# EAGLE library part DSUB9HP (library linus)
9-pin D-SUB card-mounted
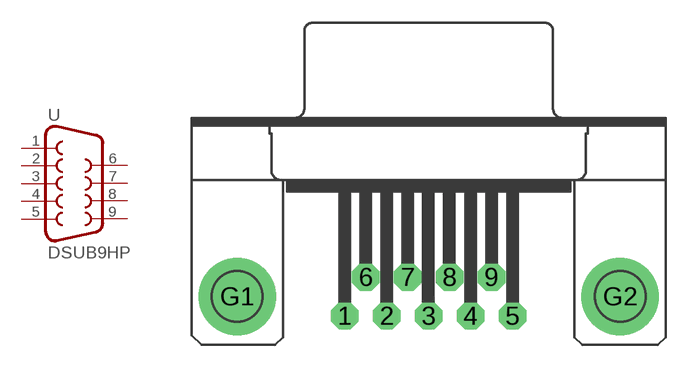
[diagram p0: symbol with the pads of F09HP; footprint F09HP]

Designator prefix -

## DSUB9HP  [F09HP]
1  1  pas
2  2  pas
3  3  pas
4  4  pas
5  5  pas
6  6  pas
7  7  pas
8  8  pas
9  9  pas

## Footprint F09HP (pad centres in mm)
drill 1.016 pad 1.778 octagon: 1 -5.486,-1.27; 2 -2.743,-1.27; 3 0,-1.27; 4 2.743,-1.27; 5 5.486,-1.27; 6 -4.115,1.27; 7 -1.372,1.27; 8 1.372,1.27; 9 4.115,1.27
drill 3.302 pad 5.08 round: G1 -12.522,0; G2 12.522,0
